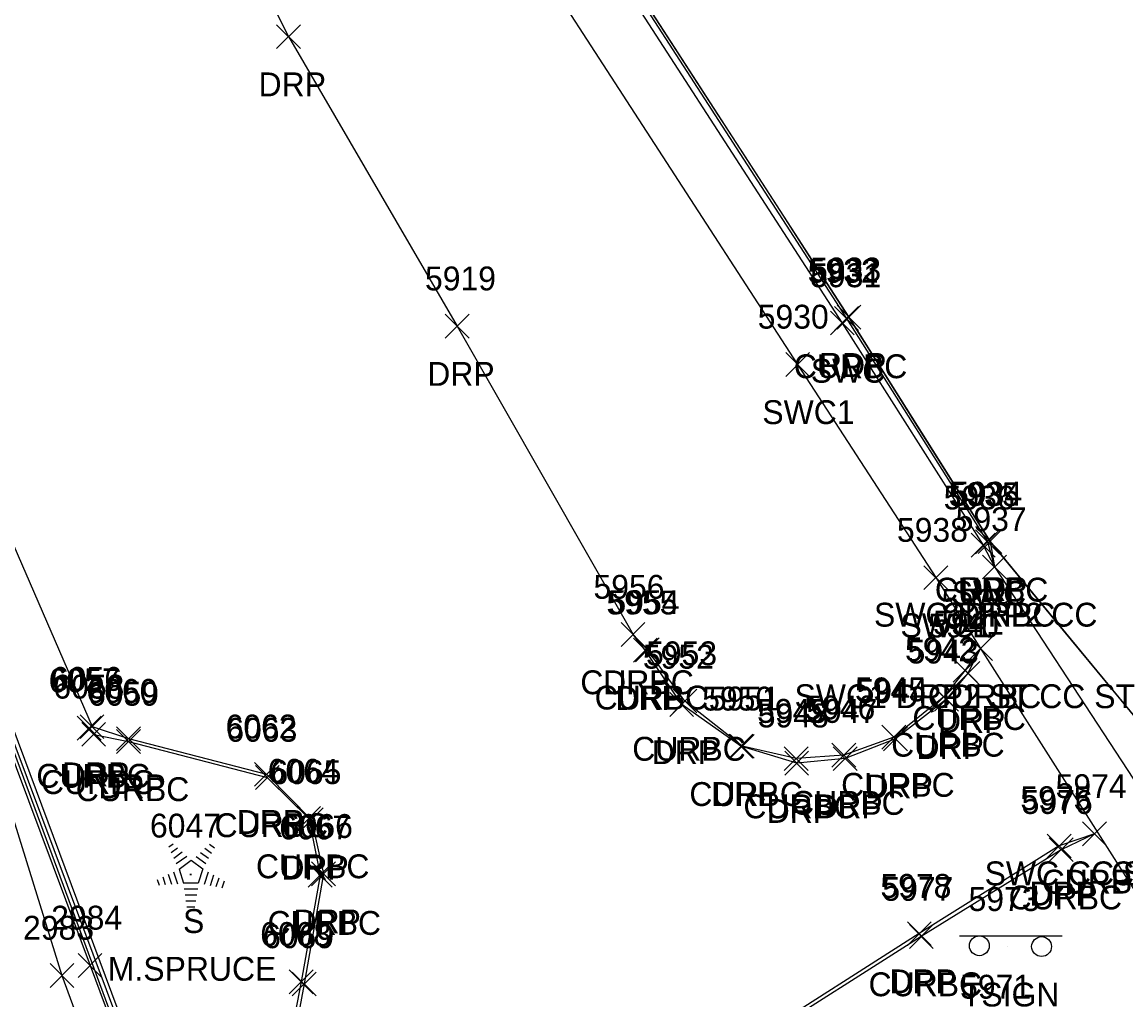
# Model space of a CAD drawing. Extents: x 1462668 to 1465147, y 550359 to 557351.
# Drawn here: x 1464443.6 to 1464536.1, y 553227.1 to 553309.1 of the extents above; entities that cross this region are included whole.
import ezdxf

# ---------------------------------------------------------------- set-up
doc = ezdxf.new("R2010")
doc.units = 0
for name, color, linetype in [('L_A', 7, 'Continuous'), ('L_C', 7, 'Continuous'), ('L_I', 7, 'Continuous'), ('L_TIC', 7, 'Continuous'), ('LELB', 7, 'Continuous'), ('Level 6', 7, 'Continuous'), ('LFNC', 7, 'Continuous'), ('LTC', 7, 'Continuous'), ('LW', 7, 'Continuous'), ('P_A', 7, 'Continuous'), ('P_I', 7, 'Continuous'), ('P_TIC', 7, 'Continuous'), ('PET', 7, 'Continuous'), ('R_A', 7, 'Continuous'), ('R_I', 7, 'Continuous'), ('R_TIC', 7, 'Continuous'), ('RC', 7, 'Continuous'), ('RDP', 7, 'Continuous'), ('RSW', 7, 'Continuous'), ('S_A', 7, 'Continuous'), ('S_I', 7, 'Continuous'), ('SSGN', 7, 'Continuous')]:
    doc.layers.add(name, color=color, linetype=linetype)

msp = doc.modelspace()

# ---------------------------------------------------------------- linework, layer by layer
at = {"layer": 'L_TIC'}
for points in [[(1464448.256, 553229.015), (1464450.256, 553231.015)], [(1464450.256, 553229.015), (1464448.256, 553231.015)], [(1464445.9, 553228.17), (1464447.9, 553230.17)], [(1464447.9, 553228.17), (1464445.9, 553230.17)]]:
    msp.add_lwpolyline(points, dxfattribs=at)
at = {"layer": 'LELB'}
for points in [[(1464399.719, 553434.969), (1464409.446, 553421.214), (1464402.249, 553418.234), (1464397.039, 553410.685), (1464397.409, 553402.739), (1464404.988, 553402.374), (1464405.18, 553391.163), (1464405.505, 553357.551), (1464416.93, 553321.523), (1464428.808, 553284.849), (1464433.809, 553271.259), (1464449.256, 553230.015), (1464470.447, 553173.076), (1464486.562, 553129.804), (1464498.303, 553097.82), (1464507.971, 553103.591)], [(1464433.809, 553271.259), (1464446.9, 553229.17), (1464467.607, 553172.811), (1464484.275, 553129.168), (1464495.72, 553097.092), (1464504.824, 553079.502), (1464512.152, 553060.642), (1464527.258, 553022.24), (1464542.187, 552990.027), (1464554.676, 552968.433)]]:
    msp.add_lwpolyline(points, dxfattribs=at)
at = {"layer": 'Level 6'}
msp.add_lwpolyline([(1464541.152, 553245.579), (1464535.656, 553252.236), (1464530.161, 553258.892), (1464524.666, 553265.549), (1464521.711, 553270.246), (1464518.757, 553274.944), (1464515.802, 553279.642), (1464512.847, 553284.339), (1464509.834, 553289.002), (1464506.821, 553293.665), (1464503.808, 553298.328), (1464500.794, 553302.991), (1464497.781, 553307.654), (1464494.768, 553312.317)], dxfattribs=at)
at = {"layer": 'LFNC'}
msp.add_lwpolyline([(1464405.682, 553401.697), (1464406.125, 553357.815), (1464412.915, 553336.379), (1464424.414, 553300.548), (1464435.201, 553269.165), (1464460.504, 553201.526), (1464472.493, 553169.782), (1464483.318, 553139.998), (1464499.045, 553098.909), (1464526.004, 553115.935), (1464547.488, 553129.548)], dxfattribs=at)
at = {"layer": 'LTC'}
for p, q in [((1464455.856, 553239.94), (1464456.211, 553240.198)), ((1464456.066, 553239.475), (1464456.595, 553239.859)), ((1464456.275, 553239.009), (1464456.979, 553239.52)), ((1464458.513, 553239.484), (1464459.192, 553238.99)), ((1464458.883, 553239.832), (1464459.433, 553239.433)), ((1464459.255, 553240.18), (1464459.674, 553239.876)), ((1464456.485, 553238.543), (1464457.363, 553239.181)), ((1464456.71, 553238.088), (1464457.721, 553238.823)), ((1464457.721, 553238.823), (1464458.718, 553238.098)), ((1464458.141, 553239.135), (1464458.951, 553238.547)), ((1464455.344, 553237.436), (1464455.556, 553236.784)), ((1464455.8, 553237.653), (1464456.071, 553236.817)), ((1464456.255, 553237.869), (1464456.586, 553236.85)), ((1464456.71, 553238.088), (1464457.097, 553236.895)), ((1464458.718, 553238.098), (1464458.327, 553236.895)), ((1464459.156, 553237.827), (1464458.818, 553236.787)), ((1464459.6, 553237.576), (1464459.313, 553236.692)), ((1464454.889, 553237.219), (1464455.041, 553236.751)), ((1464458.327, 553236.895), (1464457.097, 553236.895)), ((1464460.045, 553237.326), (1464459.808, 553236.597)), ((1464460.489, 553237.076), (1464460.303, 553236.502)), ((1464458.289, 553236.395), (1464457.144, 553236.395)), ((1464458.205, 553235.895), (1464457.217, 553235.895)), ((1464458.121, 553235.395), (1464457.29, 553235.395)), ((1464458.038, 553234.895), (1464457.363, 553234.895))]:
    msp.add_line(p, q, dxfattribs=at)
at = {"layer": 'LW'}
for points in [[(1464405.978, 553402.257), (1464405.239, 553402.286), (1464405.602, 553357.557), (1464412.384, 553336.293), (1464423.999, 553300.426), (1464435.008, 553269.098), (1464460.101, 553201.294), (1464471.952, 553169.463), (1464482.975, 553139.703), (1464498.654, 553098.241), (1464526.685, 553115.597)], [(1464405.978, 553402.257), (1464406.37, 553371.325), (1464406.561, 553357.762), (1464413.111, 553336.612), (1464424.602, 553300.656), (1464435.459, 553269.523), (1464460.732, 553201.676)]]:
    msp.add_lwpolyline(points, dxfattribs=at)
at = {"layer": 'P_TIC'}
for points in [[(1464511.847, 553283.339), (1464513.847, 553285.339)], [(1464513.847, 553283.339), (1464511.847, 553285.339)], [(1464523.666, 553264.549), (1464525.666, 553266.549)], [(1464525.666, 553264.549), (1464523.666, 553266.549)]]:
    msp.add_lwpolyline(points, dxfattribs=at)
at = {"layer": 'PET'}
msp.add_lwpolyline([(1464403.393, 553454.254), (1464404.974, 553451.612), (1464423.034, 553423.296), (1464424.684, 553420.526), (1464435.78, 553403.436), (1464440.451, 553396.43), (1464472.473, 553346.776), (1464488.742, 553321.643), (1464512.847, 553284.339), (1464524.666, 553265.549), (1464546.647, 553238.922), (1464557.393, 553222.535)], dxfattribs=at)
at = {"layer": 'R_TIC'}
for points in [[(1464464.887, 553306.857), (1464466.887, 553308.857)], [(1464466.887, 553306.857), (1464464.887, 553308.857)], [(1464479.022, 553282.59), (1464481.022, 553284.59)], [(1464481.022, 553282.59), (1464479.022, 553284.59)], [(1464511.289, 553282.854), (1464513.289, 553284.854)], [(1464513.289, 553282.854), (1464511.289, 553284.854)], [(1464511.643, 553283.229), (1464513.643, 553285.229)], [(1464513.643, 553283.229), (1464511.643, 553285.229)], [(1464507.549, 553279.384), (1464509.549, 553281.384)], [(1464509.549, 553279.384), (1464507.549, 553281.384)], [(1464523.098, 553264.23), (1464525.098, 553266.23)], [(1464525.098, 553264.23), (1464523.098, 553266.23)], [(1464523.46, 553264.509), (1464525.46, 553266.509)], [(1464525.46, 553264.509), (1464523.46, 553266.509)], [(1464523.666, 553264.549), (1464525.666, 553266.549)], [(1464525.666, 553264.549), (1464523.666, 553266.549)], [(1464524.048, 553262.41), (1464526.048, 553264.41)], [(1464526.048, 553262.41), (1464524.048, 553264.41)], [(1464524.048, 553262.41), (1464526.048, 553264.41)], [(1464526.048, 553262.41), (1464524.048, 553264.41)], [(1464524.048, 553262.41), (1464526.048, 553264.41)], [(1464526.048, 553262.41), (1464524.048, 553264.41)], [(1464519.127, 553261.517), (1464521.127, 553263.517)], [(1464521.127, 553261.517), (1464519.127, 553263.517)], [(1464493.756, 553256.744), (1464495.756, 553258.744)], [(1464495.756, 553256.744), (1464493.756, 553258.744)], [(1464493.756, 553256.744), (1464495.756, 553258.744)], [(1464495.756, 553256.744), (1464493.756, 553258.744)], [(1464493.756, 553256.744), (1464495.756, 553258.744)], [(1464495.756, 553256.744), (1464493.756, 553258.744)], [(1464494.784, 553255.431), (1464496.784, 553257.431)], [(1464496.784, 553255.431), (1464494.784, 553257.431)], [(1464494.955, 553255.462), (1464496.955, 553257.462)], [(1464496.955, 553255.462), (1464494.955, 553257.462)], [(1464522.87, 553255.575), (1464524.87, 553257.575)], [(1464524.87, 553255.575), (1464522.87, 553257.575)], [(1464522.87, 553255.575), (1464524.87, 553257.575)], [(1464524.87, 553255.575), (1464522.87, 553257.575)], [(1464522.87, 553255.575), (1464524.87, 553257.575)], [(1464524.87, 553255.575), (1464522.87, 553257.575)], [(1464521.579, 553253.747), (1464523.579, 553255.747)], [(1464523.579, 553253.747), (1464521.579, 553255.747)], [(1464521.819, 553253.499), (1464523.819, 553255.499)], [(1464523.819, 553253.499), (1464521.819, 553255.499)], [(1464498.106, 553251.17), (1464500.106, 553253.17)], [(1464500.106, 553251.17), (1464498.106, 553253.17)], [(1464519.802, 553251.512), (1464521.802, 553253.512)], [(1464521.802, 553251.512), (1464519.802, 553253.512)], [(1464520.02, 553251.318), (1464522.02, 553253.318)], [(1464522.02, 553251.318), (1464520.02, 553253.318)], [(1464497.833, 553250.884), (1464499.833, 553252.884)], [(1464499.833, 553250.884), (1464497.833, 553252.884)], [(1464448.177, 553248.904), (1464450.177, 553250.904)], [(1464450.177, 553248.904), (1464448.177, 553250.904)], [(1464448.423, 553249.026), (1464450.423, 553251.026)], [(1464450.423, 553249.026), (1464448.423, 553251.026)], [(1464448.561, 553248.376), (1464450.561, 553250.376)], [(1464450.561, 553248.376), (1464448.561, 553250.376)], [(1464451.476, 553248.02), (1464453.476, 553250.02)], [(1464453.476, 553248.02), (1464451.476, 553250.02)], [(1464451.478, 553247.784), (1464453.478, 553249.784)], [(1464453.478, 553247.784), (1464451.478, 553249.784)], [(1464515.611, 553248.146), (1464517.611, 553250.146)], [(1464517.611, 553248.146), (1464515.611, 553250.146)], [(1464515.747, 553248.009), (1464517.747, 553250.009)], [(1464517.747, 553248.009), (1464515.747, 553250.009)], [(1464502.797, 553247.384), (1464504.797, 553249.384)], [(1464504.797, 553247.384), (1464502.797, 553249.384)], [(1464502.893, 553247.376), (1464504.893, 553249.376)], [(1464504.893, 553247.376), (1464502.893, 553249.376)], [(1464511.418, 553246.635), (1464513.418, 553248.635)], [(1464513.418, 553246.635), (1464511.418, 553248.635)], [(1464507.417, 553246.344), (1464509.417, 553248.344)], [(1464509.417, 553246.344), (1464507.417, 553248.344)], [(1464507.466, 553245.962), (1464509.466, 553247.962)], [(1464509.466, 553245.962), (1464507.466, 553247.962)], [(1464511.536, 553246.343), (1464513.536, 553248.343)], [(1464513.536, 553246.343), (1464511.536, 553248.343)], [(1464463.043, 553245.033), (1464465.043, 553247.033)], [(1464465.043, 553245.033), (1464463.043, 553247.033)], [(1464463.106, 553244.764), (1464465.106, 553246.764)], [(1464465.106, 553244.764), (1464463.106, 553246.764)], [(1464466.575, 553241.32), (1464468.575, 553243.32)], [(1464468.575, 553241.32), (1464466.575, 553243.32)], [(1464466.802, 553241.215), (1464468.802, 553243.215)], [(1464468.802, 553241.215), (1464466.802, 553243.215)], [(1464532.422, 553240.037), (1464534.422, 553242.037)], [(1464534.422, 553240.037), (1464532.422, 553242.037)], [(1464532.422, 553240.037), (1464534.422, 553242.037)], [(1464534.422, 553240.037), (1464532.422, 553242.037)], [(1464529.468, 553239.026), (1464531.468, 553241.026)], [(1464531.468, 553239.026), (1464529.468, 553241.026)], [(1464529.636, 553238.71), (1464531.636, 553240.71)], [(1464531.636, 553238.71), (1464529.636, 553240.71)], [(1464467.543, 553236.575), (1464469.543, 553238.575)], [(1464469.543, 553236.575), (1464467.543, 553238.575)], [(1464467.543, 553236.575), (1464469.543, 553238.575)], [(1464469.543, 553236.575), (1464467.543, 553238.575)], [(1464467.817, 553236.697), (1464469.817, 553238.697)], [(1464469.817, 553236.697), (1464467.817, 553238.697)], [(1464517.741, 553231.676), (1464519.741, 553233.676)], [(1464519.741, 553231.676), (1464517.741, 553233.676)], [(1464517.907, 553231.432), (1464519.907, 553233.432)], [(1464519.907, 553231.432), (1464517.907, 553233.432)], [(1464465.946, 553227.645), (1464467.946, 553229.645)], [(1464467.946, 553227.645), (1464465.946, 553229.645)], [(1464466.194, 553227.459), (1464468.194, 553229.459)], [(1464468.194, 553227.459), (1464466.194, 553229.459)]]:
    msp.add_lwpolyline(points, dxfattribs=at)
at = {"layer": 'RC'}
for points in [[(1464435.78, 553403.436), (1464440.283, 553396.263), (1464472.262, 553346.621), (1464488.53, 553321.544), (1464512.643, 553284.229), (1464524.46, 553265.509), (1464525.048, 553263.41)], [(1464523.87, 553256.575), (1464522.579, 553254.747), (1464520.802, 553252.512), (1464516.611, 553249.146), (1464512.418, 553247.635), (1464508.417, 553247.344), (1464503.893, 553248.376), (1464499.106, 553252.17), (1464495.955, 553256.462), (1464494.756, 553257.744)], [(1464449.177, 553249.904), (1464449.561, 553249.376), (1464452.478, 553248.784), (1464464.106, 553245.764), (1464467.575, 553242.32), (1464468.543, 553237.575)], [(1464533.422, 553241.037), (1464530.636, 553239.71), (1464518.907, 553232.432), (1464490.806, 553214.556), (1464489.095, 553213.48)], [(1464468.543, 553237.575), (1464466.946, 553228.645), (1464465.47, 553220.99), (1464463.446, 553209.787), (1464463.998, 553203.305), (1464467.134, 553192.194), (1464475.487, 553170.86), (1464484.246, 553148.657), (1464487.641, 553142.28), (1464490.994, 553136.627), (1464495.503, 553130.929), (1464500.963, 553127.103), (1464507.415, 553124.697), (1464516.221, 553124.149), (1464522.071, 553124.782), (1464532.396, 553129.483), (1464542.271, 553135.894)]]:
    msp.add_lwpolyline(points, dxfattribs=at)
at = {"layer": 'RDP'}
for points in [[(1464432.511, 553398.348), (1464431.58, 553395.183), (1464432.758, 553391.819), (1464436.471, 553380.466), (1464443.466, 553357.898), (1464450.135, 553339.005), (1464465.887, 553307.857), (1464480.022, 553283.59), (1464494.756, 553257.744)], [(1464415.79, 553337.749), (1464428.461, 553302.553), (1464440.386, 553270.852), (1464449.423, 553250.026), (1464452.476, 553249.02), (1464464.043, 553246.033), (1464467.802, 553242.215), (1464468.817, 553237.697), (1464467.194, 553228.459), (1464465.771, 553220.817), (1464463.821, 553209.815), (1464464.173, 553203.329), (1464467.407, 553192.18), (1464475.704, 553171.123), (1464491.179, 553136.657), (1464495.726, 553131.043), (1464500.877, 553127.317), (1464507.408, 553124.811), (1464516.194, 553124.19), (1464522.185, 553124.998), (1464532.312, 553129.713), (1464542.149, 553136.009)], [(1464524.666, 553265.549), (1464525.048, 553263.41)], [(1464523.87, 553256.575), (1464522.819, 553254.499), (1464521.02, 553252.318), (1464516.747, 553249.009), (1464512.536, 553247.343), (1464508.466, 553246.962), (1464503.797, 553248.384), (1464498.833, 553251.884), (1464495.784, 553256.431), (1464494.756, 553257.744)], [(1464533.422, 553241.037), (1464530.468, 553240.026), (1464518.741, 553232.676), (1464490.747, 553214.796), (1464489.095, 553213.48)]]:
    msp.add_lwpolyline(points, dxfattribs=at)
at = {"layer": 'RSW'}
for points in [[(1464402.487, 553453.689), (1464404.242, 553451.116), (1464424.134, 553420.125), (1464435.091, 553403.037), (1464440.773, 553394.396), (1464471.773, 553346.421), (1464488.052, 553321.3), (1464512.289, 553283.854), (1464524.098, 553265.23), (1464525.048, 553263.41), (1464539.23, 553241.73), (1464543.53, 553234.823), (1464553.732, 553219.304)], [(1464398.14, 553451.664), (1464411.501, 553430.841), (1464420.346, 553417.179), (1464432.511, 553398.348), (1464436.561, 553391.97), (1464467.699, 553343.628), (1464483.906, 553318.4), (1464508.549, 553280.384), (1464520.127, 553262.517), (1464523.87, 553256.575), (1464539.365, 553232.221), (1464549.541, 553216.899)]]:
    msp.add_lwpolyline(points, dxfattribs=at)
at = {"layer": 'SSGN'}
for p, q in [((1464522.112, 553232.496), (1464530.709, 553232.496)), ((1464526.134, 553231.592), (1464526.134, 553231.592))]:
    msp.add_line(p, q, dxfattribs=at)
for centre in [(1464523.774, 553231.662), (1464528.988, 553231.592)]:
    msp.add_circle(centre, 0.833, dxfattribs=at)

# ---------------------------------------------------------------- texts
at = {"layer": 'L_A'}
msp.add_text('S', height=2, dxfattribs=at).set_placement((1464457.047, 553232.732))
at = {"layer": 'L_C'}
msp.add_text('M.SPRUCE', height=2, dxfattribs=at).set_placement((1464450.748, 553228.732))
at = {"layer": 'L_I'}
for s, p in [('6047', (1464454.275, 553240.732)), ('2984', (1464445.996, 553233.015)), ('2983', (1464443.64, 553232.17)), ('5971', (1464522.159, 553227.228))]:
    msp.add_text(s, height=2, dxfattribs=at).set_placement(p)
at = {"layer": 'LTC'}
msp.add_text('.', height=1.037, rotation=270, dxfattribs=at).set_placement((1464457.604, 553237.836))
at = {"layer": 'P_A'}
for p in [(1464510.335, 553279.339), (1464522.154, 553260.549)]:
    msp.add_text('RDP', height=2, dxfattribs=at).set_placement(p)
at = {"layer": 'P_I'}
for s, p in [('5933', (1464509.587, 553287.339)), ('5934', (1464521.406, 553268.549))]:
    msp.add_text(s, height=2, dxfattribs=at).set_placement(p)
at = {"layer": 'R_A'}
for s, p in [('DRP', (1464463.375, 553302.857)), ('CURBC', (1464508.225, 553279.229)), ('SWC', (1464509.651, 553278.854)), ('DRP', (1464477.51, 553278.59)), ('SWC1', (1464505.589, 553275.384)), ('CURBC', (1464520.043, 553260.509)), ('DRP', (1464522.154, 553260.549)), ('SWC', (1464521.46, 553260.23)), ('SWC DRP2 CC', (1464514.946, 553258.41)), ('CURBC', (1464520.631, 553258.41)), ('DRP', (1464522.536, 553258.41)), ('SWC1', (1464517.166, 553257.517)), ('CURBC', (1464490.339, 553252.744)), ('DRP', (1464492.244, 553252.744)), ('DRP', (1464492.244, 553252.744)), ('CURBC', (1464491.538, 553251.462)), ('DRP', (1464493.272, 553251.431)), ('SWC1 DRP2 ST CC ST', (1464508.287, 553251.575)), ('CURBC', (1464519.453, 553251.575)), ('DRP', (1464521.358, 553251.575)), ('CURBC', (1464518.162, 553249.747)), ('DRP', (1464520.307, 553249.499)), ('CURBC', (1464516.385, 553247.512)), ('CURBC', (1464494.689, 553247.17)), ('DRP', (1464496.321, 553246.884)), ('DRP', (1464518.508, 553247.318)), ('CURBC', (1464444.76, 553244.904)), ('DRP', (1464446.911, 553245.026)), ('CURBC', (1464445.144, 553244.376)), ('CURBC', (1464448.061, 553243.784)), ('DRP', (1464449.964, 553244.02)), ('CURBC', (1464512.193, 553244.146)), ('DRP', (1464514.235, 553244.009)), ('CURBC', (1464499.476, 553243.376)), ('DRP', (1464501.285, 553243.384)), ('CURBC', (1464504, 553242.344)), ('DRP', (1464505.954, 553241.962)), ('CURBC', (1464508.001, 553242.635)), ('DRP', (1464510.024, 553242.343)), ('DRP', (1464461.532, 553241.033)), ('CURBC', (1464459.689, 553240.764)), ('CURBC', (1464463.158, 553237.32)), ('DRP', (1464465.29, 553237.215)), ('SWC CC ST DRP ST', (1464524.214, 553236.73)), ('CURBC', (1464534.812, 553236.73)), ('CURBC', (1464529.004, 553236.037)), ('DRP', (1464530.91, 553236.037)), ('CURBC', (1464526.219, 553234.71)), ('DRP', (1464527.956, 553235.026)), ('DRP', (1464466.305, 553232.697)), ('CURBC', (1464464.126, 553232.575)), ('CURBC', (1464464.126, 553232.575)), ('CURBC', (1464514.49, 553227.432)), ('DRP', (1464516.229, 553227.676))]:
    msp.add_text(s, height=2, dxfattribs=at).set_placement(p)
at = {"layer": 'R_I'}
for s, p in [('5932', (1464509.383, 553287.229)), ('5919', (1464477.321, 553286.59)), ('5931', (1464509.596, 553286.854)), ('5930', (1464505.203, 553283.384)), ('5936', (1464520.783, 553268.23)), ('5935', (1464521.2, 553268.509)), ('5934', (1464521.406, 553268.549)), ('5937', (1464521.788, 553266.41)), ('5937', (1464521.788, 553266.41)), ('5937', (1464521.788, 553266.41)), ('5938', (1464516.867, 553265.517)), ('5956', (1464491.441, 553260.744)), ('5956', (1464491.441, 553260.744)), ('5956', (1464491.441, 553260.744)), ('5955', (1464492.524, 553259.431)), ('5954', (1464492.695, 553259.462)), ('5939', (1464520.602, 553259.575)), ('5939', (1464520.602, 553259.575)), ('5939', (1464520.602, 553259.575)), ('5941', (1464519.886, 553257.747)), ('5940', (1464519.473, 553257.499)), ('5952', (1464495.573, 553254.884)), ('5953', (1464495.846, 553255.17)), ('5942', (1464517.542, 553255.512)), ('5943', (1464517.76, 553255.318)), ('6056', (1464445.982, 553253.026)), ('6057', (1464445.791, 553252.904)), ('6058', (1464446.175, 553252.376)), ('5945', (1464513.351, 553252.146)), ('6060', (1464448.956, 553252.02)), ('6059', (1464449.084, 553251.784)), ('5950', (1464500.547, 553251.376)), ('5951', (1464501.104, 553251.384)), ('5944', (1464513.487, 553252.009)), ('5949', (1464505.149, 553250.344)), ('5946', (1464509.103, 553250.635)), ('5947', (1464509.276, 553250.343)), ('5948', (1464505.206, 553249.962)), ('6062', (1464460.61, 553249.033)), ('6063', (1464460.673, 553248.764)), ('6064', (1464464.142, 553245.32)), ('6065', (1464464.369, 553245.215)), ('5974', (1464530.162, 553244.037)), ('5974', (1464530.162, 553244.037)), ('5975', (1464527.208, 553243.026)), ('5976', (1464527.321, 553242.71)), ('6067', (1464465.11, 553240.575)), ('6067', (1464465.11, 553240.575)), ('6066', (1464465.329, 553240.697)), ('5978', (1464515.481, 553235.676)), ('5977', (1464515.647, 553235.432)), ('6068', (1464463.513, 553231.645)), ('6069', (1464463.753, 553231.459))]:
    msp.add_text(s, height=2, dxfattribs=at).set_placement(p)
at = {"layer": 'S_A'}
msp.add_text('TSIGN', height=2, dxfattribs=at).set_placement((1464522.31, 553226.574))
at = {"layer": 'S_I'}
msp.add_text('5973', height=2, dxfattribs=at).set_placement((1464522.869, 553234.574))

doc.saveas('drawing.dxf')
